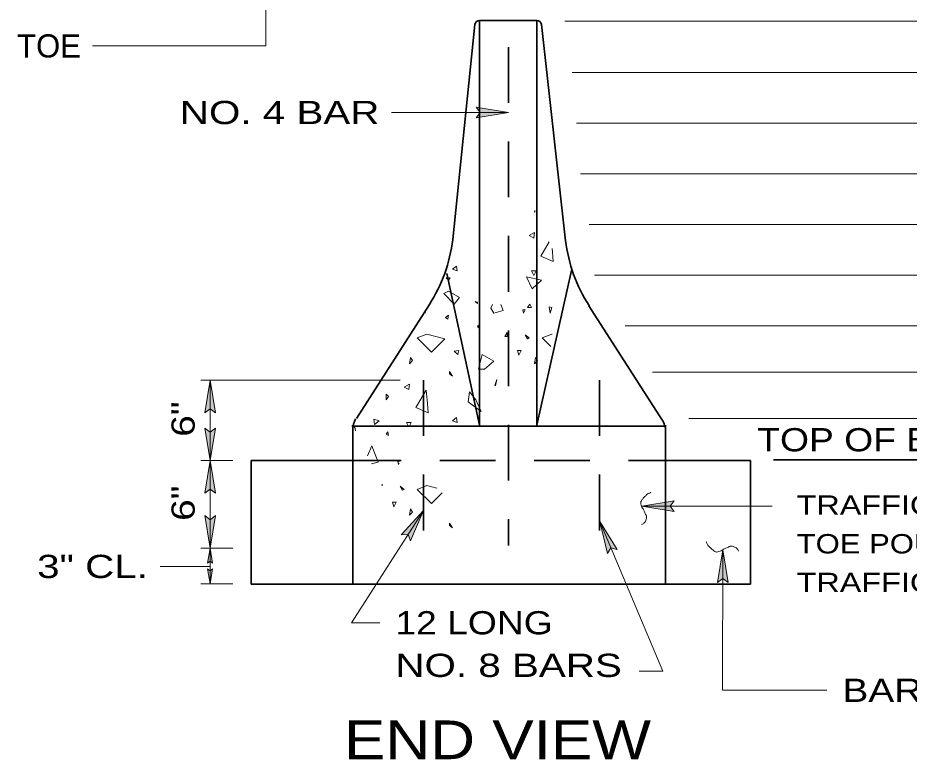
# Model space of a CAD drawing. Extents: x -11.7 to -4.5, y 8.6 to 18.8.
# Drawn here: x -11.741 to -9.437, y 15.087 to 17.003 of the extents above; entities that cross this region are included whole.
import ezdxf
from ezdxf.enums import TextEntityAlignment as Align

# ---------------------------------------------------------------- set-up
doc = ezdxf.new("R2010")
doc.units = 0
doc.header["$LTSCALE"] = 0.024
doc.linetypes.add('LONG_DASHED', pattern=[7.5, 6, -1.5])
for name, color, linetype, lineweight in [('1', 7, 'Continuous', 35), ('10', 7, 'Continuous', 13), ('12', 7, 'Continuous', 53), ('6', 7, 'Continuous', 13)]:
    doc.layers.add(name, color=color, linetype=linetype, lineweight=lineweight)

msp = doc.modelspace()

# ---------------------------------------------------------------- hatches: boundary and pattern name
at = {"layer": '10'}
for points in [[(-10.47283, 16.75883), (-10.55683, 16.77283), (-10.54633, 16.75883), (-10.55683, 16.74483)], [(-11.24417, 15.993), (-11.23017, 15.9825), (-11.24417, 16.0665), (-11.25817, 15.9825)], [(-11.24417, 15.85883), (-11.23017, 15.94283), (-11.24417, 15.93217), (-11.25817, 15.94283)], [(-11.23017, 15.77467), (-11.24417, 15.85883), (-11.25817, 15.77467), (-11.24417, 15.78533)], [(-10.1285, 15.74117), (-10.0445, 15.72717), (-10.055, 15.74117), (-10.0445, 15.75517)], [(-11.24417, 15.6325), (-11.23017, 15.7165), (-11.24417, 15.706), (-11.25817, 15.7165)], [(-10.7265, 15.65167), (-10.693, 15.73), (-10.75, 15.66683), (-10.73267, 15.66817)], [(-10.23717, 15.70117), (-10.19167, 15.62917), (-10.20867, 15.63333), (-10.21733, 15.61833)], [(-11.24417, 15.59883), (-11.23783, 15.594), (-11.24417, 15.6325), (-11.25067, 15.594)], [(-9.919, 15.55433), (-9.905, 15.54383), (-9.919, 15.62783), (-9.933, 15.54383)], [(-11.24417, 15.54017), (-11.23783, 15.57867), (-11.24417, 15.57383), (-11.25067, 15.57867)]]:
    msp.add_hatch(color=256, dxfattribs=at).paths.add_polyline_path(points)

# ---------------------------------------------------------------- linework, layer by layer
at = {"layer": '1'}
for p, q in [((-10.55983, 16.986), (-10.61717, 16.43)), ((-10.548, 15.9505), (-10.548, 16.99683)), ((-10.39967, 16.99683), (-10.548, 16.99683)), ((-10.39967, 16.99683), (-10.39967, 15.9505)), ((-10.38767, 16.98617), (-10.32517, 16.42733)), ((-10.548, 15.9505), (-10.6325, 16.34233)), ((-10.39967, 15.9505), (-10.31033, 16.35017)), ((-10.866, 15.968), (-10.6775, 16.262)), ((-10.26483, 16.25933), (-10.07633, 15.96533)), ((-10.06933, 15.948), (-10.87817, 15.948)), ((-10.8755, 15.53967), (-10.8755, 15.9505)), ((-10.06683, 15.9505), (-10.06683, 15.53967)), ((-11.138, 15.53967), (-11.138, 15.85917)), ((-11.138, 15.85917), (-10.8945, 15.85917)), ((-9.84767, 15.85917), (-10.08583, 15.85917)), ((-8.1665, 15.8605), (-9.78767, 15.8605))]:
    msp.add_line(p, q, dxfattribs=at)
at = {"layer": '1', "linetype": 'LONG_DASHED'}
for p, q in [((-10.47283, 16.9275), (-10.47283, 15.639)), ((-10.693, 16.0665), (-10.693, 15.6325)), ((-10.2375, 16.0665), (-10.2375, 15.65267)), ((-10.8945, 15.85917), (-10.08583, 15.85917))]:
    msp.add_line(p, q, dxfattribs=at)
at = {"layer": '1'}
msp.add_lwpolyline([(-9.84767, 15.85917), (-9.84767, 15.53967), (-11.138, 15.53967)], dxfattribs=at)
for centre, radius, start, end in [((-10.54795, 16.98477), 0.012, 90, 174.09074), ((-10.39964, 16.98477), 0.012, 6.42106, 90), ((-11.01437, 16.47794), 0.40006, 327.34438, 353.12306), ((-9.92799, 16.4753), 0.40006, 186.87694, 212.65562), ((-10.81554, 15.938), 0.06001, 151.69588, 180), ((-10.12683, 15.93291), 0.06001, 0, 32.65565)]:
    msp.add_arc(centre, radius, start, end, dxfattribs=at)
at = {"layer": '10'}
for p, q in [((-5.37917, 16.99467), (-10.32767, 16.99467)), ((-5.731, 16.86183), (-10.3085, 16.86183)), ((-10.77517, 16.75883), (-10.47283, 16.75883)), ((-10.55683, 16.77283), (-10.47283, 16.75883)), ((-10.55683, 16.77283), (-10.54633, 16.75883)), ((-10.55683, 16.74483), (-10.47283, 16.75883)), ((-10.55683, 16.74483), (-10.54633, 16.75883)), ((-6.0825, 16.731), (-10.2975, 16.731)), ((-6.43383, 16.6), (-10.2865, 16.6)), ((-6.78533, 16.46917), (-10.26467, 16.46917)), ((-7.13683, 16.33833), (-10.25033, 16.33833)), ((-7.48833, 16.2075), (-10.1715, 16.2075)), ((-7.92067, 16.0875), (-10.10033, 16.0875)), ((-10.753, 16.0665), (-11.26817, 16.0665)), ((-11.25817, 15.9825), (-11.24417, 16.0665)), ((-11.23017, 15.9825), (-11.24417, 16.0665)), ((-11.25817, 15.9825), (-11.24417, 15.993)), ((-11.23017, 15.9825), (-11.24417, 15.993)), ((-8.13217, 15.96733), (-10.00683, 15.96733)), ((-11.25817, 15.94283), (-11.24417, 15.85883)), ((-11.25817, 15.94283), (-11.24417, 15.93217)), ((-11.23017, 15.94283), (-11.24417, 15.85883)), ((-11.23017, 15.94283), (-11.24417, 15.93217)), ((-11.186, 15.85883), (-11.26817, 15.85883)), ((-11.25817, 15.77467), (-11.24417, 15.85883)), ((-11.23017, 15.77467), (-11.24417, 15.85883)), ((-11.25817, 15.77467), (-11.24417, 15.78533)), ((-11.23017, 15.77467), (-11.24417, 15.78533)), ((-10.0445, 15.75517), (-10.1285, 15.74117)), ((-9.7915, 15.74117), (-10.1285, 15.74117)), ((-10.0445, 15.72717), (-10.1285, 15.74117)), ((-10.0445, 15.75517), (-10.055, 15.74117)), ((-10.0445, 15.72717), (-10.055, 15.74117)), ((-11.25817, 15.7165), (-11.24417, 15.6325)), ((-11.25817, 15.7165), (-11.24417, 15.706)), ((-11.23017, 15.7165), (-11.24417, 15.6325)), ((-11.23017, 15.7165), (-11.24417, 15.706)), ((-10.87867, 15.43967), (-10.693, 15.73)), ((-10.75, 15.66683), (-10.693, 15.73)), ((-10.7265, 15.65167), (-10.693, 15.73)), ((-10.07433, 15.31417), (-10.23717, 15.70117)), ((-10.21733, 15.61833), (-10.23717, 15.70117)), ((-10.19167, 15.62917), (-10.23717, 15.70117)), ((-10.75, 15.66683), (-10.73267, 15.66817)), ((-10.7265, 15.65167), (-10.73267, 15.66817)), ((-11.26817, 15.6325), (-11.186, 15.6325)), ((-11.25067, 15.594), (-11.24417, 15.6325)), ((-11.23783, 15.594), (-11.24417, 15.6325)), ((-10.21733, 15.61833), (-10.20867, 15.63333)), ((-10.19167, 15.62917), (-10.20867, 15.63333)), ((-9.933, 15.54383), (-9.919, 15.62783)), ((-9.9195, 15.265), (-9.919, 15.62717)), ((-9.905, 15.54383), (-9.919, 15.62783)), ((-11.24417, 15.58533), (-11.37367, 15.58533)), ((-11.25067, 15.594), (-11.24417, 15.59883)), ((-11.25067, 15.57867), (-11.24417, 15.54017)), ((-11.25067, 15.57867), (-11.24417, 15.57383)), ((-11.23783, 15.594), (-11.24417, 15.59883)), ((-11.23783, 15.57867), (-11.24417, 15.54017)), ((-11.23783, 15.57867), (-11.24417, 15.57383)), ((-11.186, 15.54017), (-11.26817, 15.54017)), ((-9.933, 15.54383), (-9.919, 15.55433)), ((-9.905, 15.54383), (-9.919, 15.55433)), ((-10.8055, 15.43967), (-10.87867, 15.43967)), ((-10.1355, 15.31417), (-10.07433, 15.31417)), ((-9.64983, 15.265), (-9.9195, 15.265))]:
    msp.add_line(p, q, dxfattribs=at)
for points in [[(-11.54833, 16.931), (-11.1005, 16.931), (-11.1005, 17.24683)], [(-11.24417, 15.54017), (-11.24417, 15.6325), (-11.24417, 15.85883), (-11.24417, 16.0665)]]:
    msp.add_lwpolyline(points, dxfattribs=at)
for points in [[(-10.47283, 16.75883), (-10.55683, 16.77283), (-10.54633, 16.75883), (-10.55683, 16.74483)], [(-11.24417, 15.993), (-11.23017, 15.9825), (-11.24417, 16.0665), (-11.25817, 15.9825)], [(-11.24417, 15.85883), (-11.23017, 15.94283), (-11.24417, 15.93217), (-11.25817, 15.94283)], [(-11.23017, 15.77467), (-11.24417, 15.85883), (-11.25817, 15.77467), (-11.24417, 15.78533)], [(-10.1285, 15.74117), (-10.0445, 15.72717), (-10.055, 15.74117), (-10.0445, 15.75517)], [(-11.24417, 15.6325), (-11.23017, 15.7165), (-11.24417, 15.706), (-11.25817, 15.7165)], [(-10.7265, 15.65167), (-10.693, 15.73), (-10.75, 15.66683), (-10.73267, 15.66817)], [(-10.23717, 15.70117), (-10.19167, 15.62917), (-10.20867, 15.63333), (-10.21733, 15.61833)], [(-11.24417, 15.59883), (-11.23783, 15.594), (-11.24417, 15.6325), (-11.25067, 15.594)], [(-9.919, 15.55433), (-9.905, 15.54383), (-9.919, 15.62783), (-9.933, 15.54383)], [(-11.24417, 15.54017), (-11.23783, 15.57867), (-11.24417, 15.57383), (-11.25067, 15.57867)]]:
    msp.add_lwpolyline(points, close=True, dxfattribs=at)
for points in [[(-10.12933, 15.69367), (-10.125, 15.69517), (-10.122, 15.698), (-10.11917, 15.70083), (-10.11767, 15.70517), (-10.11633, 15.7095), (-10.11633, 15.71517), (-10.12067, 15.724), (-10.122, 15.72833), (-10.12633, 15.7355), (-10.13067, 15.747), (-10.13067, 15.75283), (-10.12783, 15.75717), (-10.1235, 15.76283), (-10.11767, 15.76867), (-10.1135, 15.773), (-10.10617, 15.77583), (-10.10483, 15.77733)], [(-9.8785, 15.62433), (-9.87983, 15.62867), (-9.88283, 15.6315), (-9.88567, 15.6345), (-9.89, 15.63583), (-9.89433, 15.63733), (-9.9, 15.63733), (-9.90883, 15.633), (-9.913, 15.6315), (-9.92033, 15.62717), (-9.93183, 15.62283), (-9.93767, 15.62283), (-9.942, 15.62583), (-9.94767, 15.63017), (-9.9535, 15.63583), (-9.95783, 15.64017), (-9.96067, 15.64733), (-9.962, 15.64883)]]:
    msp.add_spline(points, degree=3, dxfattribs=at)
at = {"layer": '6'}
for points in [[(-10.40517, 16.50533), (-10.40583, 16.501), (-10.404, 16.50283)], [(-10.36033, 16.40733), (-10.35933, 16.39783), (-10.35733, 16.37383), (-10.3895, 16.38767), (-10.368, 16.424)], [(-10.6885, 16.24333), (-10.68817, 16.24033), (-10.6865, 16.24667)], [(-10.51433, 16.2625), (-10.51867, 16.25283), (-10.5105, 16.24033), (-10.4865, 16.2465), (-10.49267, 16.2625)], [(-10.36383, 16.15417), (-10.38567, 16.176), (-10.36117, 16.186), (-10.36033, 16.18583)], [(-10.72833, 15.9505), (-10.72467, 15.9575), (-10.73667, 15.9575), (-10.73317, 15.9505)], [(-10.86833, 15.9355), (-10.86817, 15.9355), (-10.87, 15.9455), (-10.87233, 15.94383)], [(-10.827, 15.85033), (-10.8095, 15.85483), (-10.82583, 15.897), (-10.83717, 15.87133)], [(-10.75517, 15.85667), (-10.75917, 15.85667), (-10.75717, 15.8485), (-10.75517, 15.85233)], [(-10.7995, 15.79333), (-10.7995, 15.79817), (-10.80083, 15.796)], [(-10.64483, 15.77517), (-10.67233, 15.74767), (-10.70883, 15.78417), (-10.68433, 15.79433), (-10.65817, 15.7875)]]:
    msp.add_lwpolyline(points, dxfattribs=at)
for points in [[(-10.41983, 16.4405), (-10.40783, 16.43417), (-10.40583, 16.44867)], [(-10.6075, 16.36183), (-10.6175, 16.35367), (-10.6055, 16.34933)], [(-10.4135, 16.34933), (-10.40783, 16.33733), (-10.4015, 16.34933)], [(-10.63383, 16.3315), (-10.62767, 16.32533), (-10.62383, 16.3315)], [(-10.426, 16.3335), (-10.41167, 16.30317), (-10.38767, 16.32533)], [(-10.64017, 16.29117), (-10.61367, 16.26283), (-10.59933, 16.28067), (-10.62767, 16.297)], [(-10.55317, 16.26867), (-10.559, 16.2705), (-10.55317, 16.26483)], [(-10.436, 16.2485), (-10.43417, 16.24033), (-10.42983, 16.2485)], [(-10.41783, 16.26283), (-10.4135, 16.25467), (-10.42367, 16.25467)], [(-10.3675, 16.25667), (-10.365, 16.24033), (-10.36117, 16.25467)], [(-10.63583, 16.22833), (-10.63, 16.2245), (-10.62767, 16.2345)], [(-10.54883, 16.21), (-10.55317, 16.20617), (-10.55083, 16.20183)], [(-10.68433, 16.186), (-10.63767, 16.174), (-10.67233, 16.1395), (-10.70883, 16.176)], [(-10.47633, 16.18983), (-10.48217, 16.17983), (-10.47633, 16.17983)], [(-10.42367, 16.174), (-10.41983, 16.176), (-10.42983, 16.18417)], [(-10.61367, 16.14133), (-10.60367, 16.13317), (-10.60167, 16.14333)], [(-10.535, 16.09483), (-10.5105, 16.1155), (-10.54067, 16.13317), (-10.55083, 16.09483)], [(-10.45, 16.14333), (-10.44617, 16.13133), (-10.44, 16.14333)], [(-10.7265, 16.1255), (-10.729, 16.10917), (-10.72083, 16.11733)], [(-10.4035, 16.1255), (-10.40583, 16.10917), (-10.39767, 16.11733)], [(-10.62567, 16.089), (-10.62567, 16.08283), (-10.6175, 16.077)], [(-10.5085, 16.05267), (-10.50667, 16.05267), (-10.50283, 16.06883)], [(-10.74283, 16.04867), (-10.73083, 16.0425), (-10.729, 16.05683)], [(-10.68233, 16.006), (-10.6805, 15.982), (-10.71267, 15.996), (-10.68617, 16.0405)], [(-10.78933, 16.0305), (-10.78933, 16.01617), (-10.78317, 16.02433)], [(-10.57333, 16.03633), (-10.57717, 16.01033), (-10.54317, 15.98583), (-10.557, 16.01617)], [(-10.6075, 15.97), (-10.6175, 15.96183), (-10.6055, 15.9575)], [(-10.8215, 15.96567), (-10.81967, 15.95183), (-10.80767, 15.96183)], [(-10.78933, 15.92733), (-10.78317, 15.9235), (-10.78517, 15.9335)], [(-10.74667, 15.78233), (-10.74283, 15.78417), (-10.753, 15.79233)], [(-10.77317, 15.7515), (-10.76933, 15.7395), (-10.763, 15.7515)], [(-10.7265, 15.73383), (-10.729, 15.7175), (-10.72083, 15.72567)], [(-10.62567, 15.69733), (-10.62567, 15.69117), (-10.6175, 15.68533)]]:
    msp.add_lwpolyline(points, close=True, dxfattribs=at)

# ---------------------------------------------------------------- texts
at = {"layer": '12'}
msp.add_text('TOE', height=0.06001, dxfattribs=at).set_placement((-11.74325, 16.90092))
for s, width, p in [('NO. 4 BAR', 1.3, (-10.80667, 16.72875)), ('TOP OF BARRIER FOOTER', 1.2, (-8.58858, 15.88275)), ('3" CL.', 1.3, (-11.40517, 15.55525))]:
    msp.add_text(s, height=0.06001, dxfattribs=dict(at, width=width)).set_placement(p, align=Align.RIGHT)
at = {"layer": '12', "width": 1.25}
for p in [(-11.28425, 15.96617), (-11.28425, 15.74867)]:
    msp.add_text('6"', height=0.06001, rotation=90, dxfattribs=at).set_placement(p, align=Align.CENTER)
at = {"layer": '12'}
for s, height, width, p in [('TRAFFIC BARRIER END TRANSITION', 0.05001, 1.25, (-9.72792, 15.71883)), ('TOE POURED MONOLITHIC WITH THE', 0.05001, 1.2, (-9.72792, 15.61883)), ('TRAFFIC BARRIER END TRANSITION', 0.05001, 1.25, (-9.72792, 15.51883)), ('12 LONG', 0.06001, 1.2, (-10.76542, 15.40958)), ('NO. 8 BARS', 0.06001, 1.3, (-10.76542, 15.2995)), ('BARRIER FOOTER (SEE NOTE 1)', 0.06001, 1.25, (-9.60967, 15.23492))]:
    msp.add_text(s, height=height, dxfattribs=dict(at, width=width)).set_placement(p)
at = {"layer": '12', "width": 1.2}
msp.add_text('END VIEW', height=0.1, dxfattribs=at).set_placement((-10.50146, 15.08692), align=Align.CENTER)

doc.saveas('drawing.dxf')
